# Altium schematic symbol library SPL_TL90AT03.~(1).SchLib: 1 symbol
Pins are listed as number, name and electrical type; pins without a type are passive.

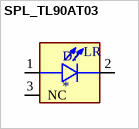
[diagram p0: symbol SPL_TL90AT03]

## SPL_TL90AT03
designator D?
Laser Diode 905nm 65W 9.5V 20A TO-56-3 Lens Top Metal Can; MF: OSRAM Opto (ams OSRAM); MP: SPL TL90AT03
footprint TO100P560H400-3
pins: 1 LD_A, 2 LD_C, 3 NC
